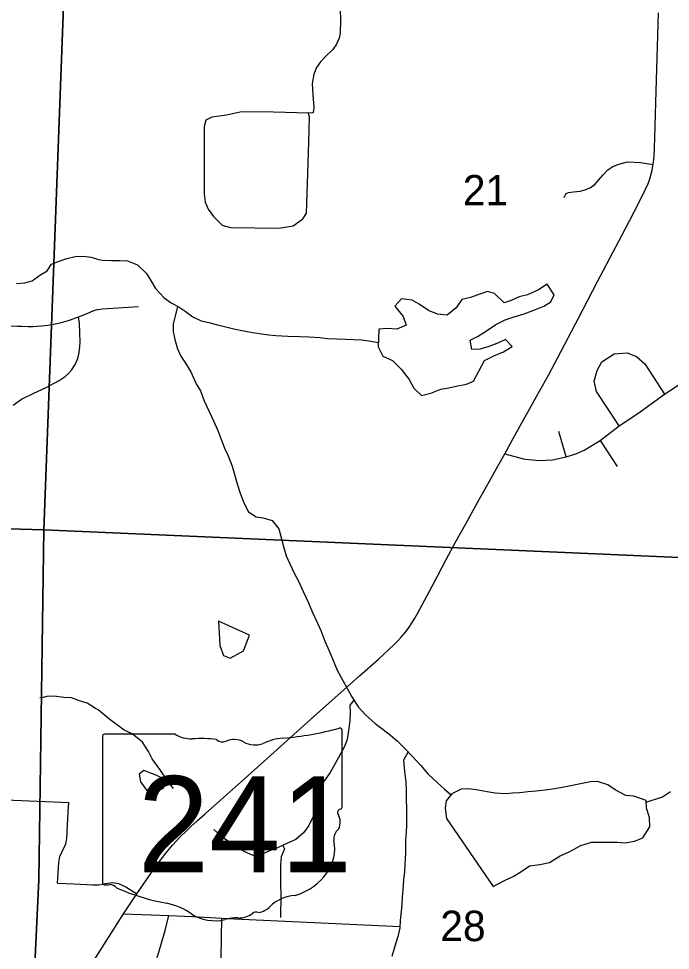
# Model space of a CAD drawing. Extents: x 0 to 34, y 0 to 22.
# Drawn here: x 5.169 to 6.064, y 16.375 to 17.654 of the extents above; entities that cross this region are included whole.
import ezdxf

# ---------------------------------------------------------------- set-up
doc = ezdxf.new("R2010")
doc.units = 0
for name, color, linetype in [('GM_X_Corporation', 7, 'Continuous'), ('GM_X_Minor_Lake', 7, 'Continuous'), ('GM_X_Minor_River', 7, 'Continuous'), ('GM_X_Section_Text', 7, 'Continuous'), ('GM_X_State_Location', 7, 'Continuous'), ('GM_X_State_Route', 7, 'Continuous'), ('GM_X_State_Shield', 7, 'Continuous'), ('GM_X_Township_Road', 7, 'Continuous')]:
    doc.layers.add(name, color=color, linetype=linetype)

msp = doc.modelspace()

# ---------------------------------------------------------------- linework, layer by layer
at = {"layer": 'GM_X_Corporation'}
for points in [[(4.2238, 17.9879), (5.2412, 17.9526), (5.2034, 16.9522), (4.1823, 16.9818)], [(5.2412, 17.9526), (6.2808, 17.9117), (6.2453, 16.9071), (5.2034, 16.9522)], [(5.2034, 16.9522), (5.1967, 16.4715), (5.1712, 15.9307), (4.1402, 15.964), (4.1823, 16.9818)], [(5.2034, 16.9522), (6.2453, 16.9071), (6.2042, 15.8911), (5.1712, 15.9307), (5.1967, 16.4715)]]:
    msp.add_lwpolyline(points, close=True, dxfattribs=at)
at = {"layer": 'GM_X_Minor_Lake'}
for points in [[(5.8087, 17.1849), (5.8219, 17.1912), (5.8351, 17.1967), (5.8468, 17.2041), (5.8379, 17.2138), (5.8281, 17.2091), (5.8164, 17.2044), (5.8028, 17.2004), (5.7915, 17.1999), (5.789, 17.2128), (5.7992, 17.2178), (5.8105, 17.2245), (5.8244, 17.2345), (5.8372, 17.2408), (5.8497, 17.2448), (5.8633, 17.2491), (5.8765, 17.2539), (5.8904, 17.2594), (5.9002, 17.2656), (5.9046, 17.2752), (5.895, 17.2895), (5.8829, 17.2821), (5.8682, 17.275), (5.8565, 17.2722), (5.8456, 17.2671), (5.8357, 17.2639), (5.8227, 17.2767), (5.8128, 17.2796), (5.7996, 17.2752), (5.7897, 17.2713), (5.7776, 17.2688), (5.7698, 17.2573), (5.7578, 17.2469), (5.7445, 17.2486), (5.7319, 17.2534), (5.7193, 17.2623), (5.7097, 17.2679), (5.6949, 17.2696), (5.6856, 17.2596), (5.6972, 17.2453), (5.7015, 17.2332), (5.6887, 17.2277), (5.6754, 17.2286), (5.6636, 17.2281), (5.6631, 17.2144), (5.6628, 17.2038), (5.6691, 17.1909), (5.6824, 17.1847), (5.6943, 17.1731), (5.7055, 17.1588), (5.7118, 17.1471), (5.7222, 17.1366), (5.7354, 17.1402), (5.749, 17.1453), (5.7599, 17.1474), (5.7698, 17.1498), (5.7842, 17.1523), (5.794, 17.1566)], [(5.794, 17.1566), (5.8087, 17.1849)], [(5.4434, 16.8268), (5.4453, 16.7934), (5.4504, 16.7798), (5.4596, 16.7761), (5.4777, 16.7863), (5.4861, 16.8077)], [(5.4861, 16.8077), (5.4434, 16.8268)], [(5.3411, 16.6217), (5.3347, 16.6167), (5.3363, 16.6061), (5.3464, 16.5925), (5.3563, 16.59), (5.3623, 16.595), (5.3683, 16.5986), (5.3675, 16.6042), (5.3643, 16.6122), (5.359, 16.6148)], [(5.359, 16.6148), (5.3411, 16.6217)], [(5.8208, 16.4624), (5.8363, 16.4706), (5.8483, 16.4761), (5.8589, 16.4827), (5.8709, 16.4909), (5.8849, 16.4926), (5.8982, 16.4954), (5.9128, 16.5048), (5.926, 16.5106), (5.9411, 16.5188), (5.9558, 16.5232), (5.9676, 16.5234), (5.9801, 16.5232), (5.9911, 16.5233), (6.0021, 16.5227), (6.015, 16.5248), (6.0263, 16.5295), (6.036, 16.5445), (6.0354, 16.5574), (6.0314, 16.5703), (6.0309, 16.5805), (6.0141, 16.5867), (6.0031, 16.5873), (5.9882, 16.5955), (5.9783, 16.6022), (5.9642, 16.6069), (5.9547, 16.6064), (5.9407, 16.6036), (5.9252, 16.6003), (5.9135, 16.5979), (5.9025, 16.5962), (5.8923, 16.5949), (5.8798, 16.5936), (5.8688, 16.5923), (5.857, 16.591), (5.8472, 16.5905), (5.8377, 16.59), (5.8236, 16.5909), (5.8126, 16.5923), (5.7974, 16.5955), (5.7864, 16.5968), (5.7769, 16.5963), (5.7641, 16.5897), (5.7563, 16.5801), (5.7549, 16.5702), (5.7566, 16.5558)], [(5.7566, 16.5558), (5.8208, 16.4624)], [(5.7566, 16.5558), (5.821, 16.4625)]]:
    msp.add_lwpolyline(points, dxfattribs=at)
at = {"layer": 'GM_X_Minor_River'}
for points in [[(5.1662, 17.2905), (5.1775, 17.2913), (5.1877, 17.2944), (5.1983, 17.302), (5.2082, 17.3078), (5.2142, 17.3173), (5.2248, 17.3215), (5.2354, 17.325), (5.2467, 17.3277), (5.2574, 17.3281), (5.2687, 17.3266), (5.2786, 17.3236), (5.2843, 17.3225)], [(5.2843, 17.3225), (5.2967, 17.3221), (5.3073, 17.3223), (5.3187, 17.3217), (5.3324, 17.3161), (5.3447, 17.3042), (5.3509, 17.2936), (5.3571, 17.2838), (5.3687, 17.2707), (5.3786, 17.264), (5.3882, 17.2588), (5.3977, 17.2525), (5.4081, 17.245), (5.4199, 17.2395), (5.4302, 17.237), (5.4405, 17.2345), (5.4538, 17.2312), (5.4648, 17.2283), (5.4778, 17.2255), (5.4907, 17.2234), (5.5025, 17.2217), (5.5128, 17.2203), (5.5222, 17.2193), (5.5386, 17.2184), (5.5549, 17.2178), (5.5678, 17.2173), (5.5826, 17.2163), (5.5932, 17.2153), (5.6061, 17.2147), (5.6179, 17.2142), (5.6289, 17.2139), (5.6399, 17.2133), (5.6502, 17.2119), (5.6631, 17.2095)], [(5.3874, 17.2592), (5.3813, 17.2348), (5.3811, 17.2249), (5.3835, 17.2139), (5.3871, 17.201), (5.3918, 17.1908), (5.398, 17.181), (5.4053, 17.1694), (5.4128, 17.1528), (5.4186, 17.143), (5.4237, 17.1294), (5.4307, 17.115), (5.4366, 17.1018), (5.4428, 17.0886), (5.448, 17.0742), (5.4523, 17.0636), (5.457, 17.0538), (5.4621, 17.0398), (5.4661, 17.027), (5.4692, 17.0156), (5.4732, 17.0028), (5.4783, 16.9895), (5.4846, 16.9771), (5.4953, 16.97), (5.5048, 16.9686), (5.5174, 16.965), (5.5262, 16.9537), (5.5302, 16.9401), (5.5326, 16.9295), (5.5366, 16.9167), (5.5413, 16.9057), (5.5479, 16.8921), (5.5534, 16.8819), (5.56, 16.8676), (5.5671, 16.8521), (5.5726, 16.8389), (5.5796, 16.8242), (5.5839, 16.814), (5.5894, 16.7996), (5.5957, 16.786), (5.6, 16.7754), (5.6066, 16.7596), (5.6121, 16.7494), (5.6191, 16.737), (5.6265, 16.723), (5.6354, 16.7091), (5.645, 16.6986), (5.6585, 16.6862), (5.6696, 16.678), (5.6796, 16.6702), (5.6895, 16.662), (5.6999, 16.6518), (5.7095, 16.6417), (5.7211, 16.629), (5.7315, 16.6166), (5.7438, 16.6053), (5.7538, 16.5964), (5.7632, 16.5886)], [(5.2784, 16.7052), (5.2746, 16.7071), (5.2632, 16.7143), (5.2526, 16.7177), (5.2416, 16.7214), (5.231, 16.7221), (5.2211, 16.7236), (5.2097, 16.7239), (5.1991, 16.7213), (5.1987, 16.722)], [(5.6293, 16.7186), (5.624, 16.7116), (5.6245, 16.7017), (5.6239, 16.6899), (5.6222, 16.6766), (5.6201, 16.6644), (5.616, 16.6537), (5.6035, 16.6307), (5.5968, 16.6192), (5.589, 16.6081), (5.5827, 16.5951), (5.5791, 16.5787), (5.5752, 16.5623), (5.5674, 16.5463), (5.5604, 16.5363), (5.5499, 16.527), (5.534, 16.52), (5.5238, 16.5153), (5.5137, 16.5113), (5.5008, 16.5054), (5.491, 16.5049), (5.4795, 16.5101), (5.4638, 16.5197), (5.4501, 16.5294), (5.437, 16.541)], [(5.3816, 16.5972), (5.3739, 16.6074), (5.3634, 16.6228), (5.3526, 16.6378), (5.3472, 16.648), (5.339, 16.6608), (5.3248, 16.6724), (5.3141, 16.6772), (5.3047, 16.6842), (5.2947, 16.6912), (5.2784, 16.7052)], [(5.7041, 16.6475), (5.6975, 16.6359), (5.6992, 16.6207), (5.7009, 16.6063), (5.7014, 16.5941), (5.7019, 16.5576), (5.7017, 16.5474), (5.7011, 16.5367), (5.7005, 16.5257), (5.7003, 16.5082), (5.6994, 16.4926), (5.6988, 16.4831), (5.6978, 16.4717), (5.6968, 16.458), (5.6958, 16.4485), (5.6952, 16.4375), (5.6932, 16.4158), (5.6926, 16.4059), (5.6898, 16.3937), (5.6858, 16.3807), (5.6814, 16.3662)], [(6.031, 16.5784), (6.0536, 16.5858), (6.0645, 16.5931)], [(5.5319, 16.519), (5.5341, 16.5143), (5.5297, 16.5032), (5.5287, 16.4925), (5.5286, 16.4758), (5.529, 16.4412), (5.5288, 16.4298), (5.5289, 16.42)]]:
    msp.add_lwpolyline(points, dxfattribs=at)
at = {"layer": 'GM_X_State_Route'}
for points in [[(5.9642, 17.2932), (5.9725, 17.309), (6.002, 17.3654), (6.0214, 17.4022), (6.0302, 17.4201), (6.0337, 17.428), (6.0359, 17.4342), (6.0387, 17.4443), (6.0407, 17.4542), (6.042, 17.4649), (6.0426, 17.4763), (6.0432, 17.5064), (6.0441, 17.5394), (6.048, 17.6624)], [(5.3131, 16.4252), (5.3312, 16.4526), (5.3577, 16.4907), (5.371, 16.5082), (5.3803, 16.5194), (5.3907, 16.5305), (5.3986, 16.5382), (5.4061, 16.5452), (5.4147, 16.5531), (5.4251, 16.5623), (5.4462, 16.5813), (5.4749, 16.6069), (5.5058, 16.6341), (5.57, 16.6918), (5.637, 16.7516), (5.6632, 16.7749), (5.6849, 16.7949), (5.6898, 16.7998), (5.6942, 16.8046), (5.6974, 16.8082), (5.7003, 16.8118), (5.7053, 16.8186), (5.7096, 16.8251), (5.7132, 16.8312), (5.7168, 16.8375), (5.7202, 16.8435), (5.7233, 16.8495), (5.7332, 16.8679), (5.7442, 16.8887), (5.7564, 16.9118), (5.7696, 16.9362), (5.7833, 16.9607), (5.7994, 16.9897), (5.8157, 17.019), (5.8273, 17.0396), (5.8369, 17.0567), (5.8512, 17.0828), (5.8805, 17.1355), (5.8967, 17.1648), (5.9097, 17.189), (5.9379, 17.243), (5.9504, 17.2668), (5.9642, 17.2932)], [(5.2042, 16.248), (5.2124, 16.2632), (5.2218, 16.279), (5.232, 16.2955), (5.2494, 16.3232), (5.2656, 16.3495), (5.2775, 16.3685), (5.2957, 16.3977), (5.3131, 16.4252)]]:
    msp.add_lwpolyline(points, dxfattribs=at)
at = {"layer": 'GM_X_State_Shield'}
for p, q in [((5.6136, 16.572), (5.6136, 16.6766)), ((5.284, 16.6682), (5.284, 16.4681)), ((5.3838, 16.6717), (5.2872, 16.6717)), ((5.6136, 16.572), (5.6136, 16.572))]:
    msp.add_line(p, q, dxfattribs=at)
for centre, major_axis, start_param, end_param in [((5.4962, 16.9445), (0.3495, 0), 4.814394, 5.042369), ((5.6099, 16.6771), (0.00367, 0), 6.141152, 7.989035), ((5.2878, 16.6687), (0.00382, 0), 1.712693, 3.28349), ((5.4068, 16.6949), (0.037, 0), 4.042523, 4.731795), ((5.419, 16.5593), (0.133, 0), 1.404758, 1.657858), ((5.4492, 16.6697), (0.0107, 0), 3.836095, 5.185415), ((5.4649, 16.6466), (0.0222, 0), 0.950623, 2.079405), ((5.4936, 16.6783), (0.0267, 0), 4.081561, 5.145723), ((5.5408, 16.6106), (0.0703, 0), 1.699011, 2.107814), ((5.6097, 16.5716), (0.00393, 0), 5.05454, 6.418171), ((5.6127, 16.5643), (0.00568, 0), 1.883978, 3.671073), ((5.5766, 16.551), (0.0341, 0), 5.934695, 6.695948), ((5.6267, 16.5281), (0.0248, 0), 2.387724, 3.262537), ((5.5158, 16.5148), (0.0874, 0), 5.101752, 6.440018), ((5.2878, 16.4677), (0.00385, 0), 3.00124, 4.508301), ((5.2884, 16.4882), (0.0294, 0), 4.665946, 4.897461), ((5.2944, 16.4566), (0.0106, 0), 0.519207, 1.627899), ((5.4282, 16.6364), (0.2524, 0), 4.195997, 4.488961), ((5.5526, 16.4119), (0.0479, 0), 1.647645, 2.488434), ((5.353, 16.3782), (0.079, 0), 0.823519, 1.323587), ((5.492, 16.4487), (0.0282, 0), 4.937069, 5.64225), ((5.4384, 16.4556), (0.0501, 0), 4.026481, 4.996735), ((5.4674, 16.3864), (0.0412, 0), 1.495662, 1.94098), ((5.471, 16.4406), (0.0267, 0), 4.691044, 5.507374), ((5.4952, 16.4212), (0.00752, 0), 1.147584, 2.315152)]:
    msp.add_ellipse(centre, major_axis=major_axis, ratio=0.8, start_param=start_param, end_param=end_param, dxfattribs=at)
at = {"layer": 'GM_X_Township_Road'}
for p, q in [((5.921, 17.0526), (5.9109, 17.0874)), ((5.9679, 17.0752), (5.991, 17.0392)), ((5.4557, 16.4187), (5.6929, 16.4076))]:
    msp.add_line(p, q, dxfattribs=at)
for points in [[(5.6104, 17.6776), (5.6112, 17.6534), (5.6108, 17.6346), (5.6091, 17.6276), (5.6056, 17.6192), (5.6007, 17.612), (5.5967, 17.6083)], [(5.5967, 17.6083), (5.5928, 17.6045), (5.5834, 17.5949), (5.5783, 17.5872), (5.5746, 17.5783), (5.5721, 17.5652), (5.573, 17.5496), (5.5743, 17.5328), (5.5735, 17.5252), (5.5668, 17.5245), (5.5357, 17.5255)], [(5.5357, 17.5255), (5.5192, 17.5261), (5.4751, 17.5263), (5.4547, 17.5218), (5.4342, 17.5189), (5.4262, 17.5149), (5.4237, 17.5062), (5.424, 17.4864), (5.424, 17.4427), (5.4238, 17.4235)], [(5.5661, 17.4415), (5.5674, 17.4846), (5.5687, 17.5194), (5.567, 17.5239)], [(5.9184, 17.4089), (5.921, 17.414), (5.9243, 17.4158), (5.931, 17.4163), (5.9405, 17.4173), (5.9474, 17.4191), (5.9538, 17.4222), (5.9599, 17.4263), (5.9655, 17.4324), (5.9717, 17.4398), (5.9783, 17.4467), (5.985, 17.4511), (5.9935, 17.4547), (6.0052, 17.4575), (6.0233, 17.457), (6.0407, 17.4542)], [(5.4513, 17.3698), (5.4602, 17.3676), (5.5266, 17.3665), (5.5461, 17.3697), (5.5594, 17.3795), (5.5645, 17.3874), (5.5661, 17.4415)], [(5.4238, 17.4235), (5.4237, 17.4134), (5.4251, 17.4022), (5.4295, 17.3925), (5.4367, 17.3827), (5.4486, 17.3705), (5.4513, 17.3698)], [(5.1419, 17.2309), (5.1505, 17.2323), (5.1671, 17.2322), (5.1728, 17.2318), (5.182, 17.2317), (5.1891, 17.2316), (5.194, 17.2319), (5.2007, 17.2325), (5.2093, 17.2336), (5.2169, 17.2348), (5.2259, 17.2367), (5.239, 17.2403), (5.2514, 17.2448), (5.2629, 17.2495), (5.2724, 17.2534), (5.2774, 17.2549), (5.284, 17.2558), (5.3334, 17.2589)], [(5.1616, 17.1237), (5.1728, 17.1318), (5.1899, 17.1398), (5.2067, 17.1478), (5.2248, 17.1573), (5.2331, 17.163), (5.2375, 17.1671), (5.2414, 17.1716), (5.2466, 17.1795), (5.2501, 17.1876), (5.2518, 17.1937), (5.2532, 17.203), (5.2534, 17.2111), (5.2531, 17.222), (5.2524, 17.2361), (5.2514, 17.2448)], [(5.9941, 17.0952), (5.9627, 17.1421), (5.9596, 17.1566), (5.9638, 17.1712), (5.97, 17.1831), (5.9868, 17.1938), (6.0048, 17.1953), (6.0175, 17.1903), (6.029, 17.1804), (6.056, 17.1388)], [(5.8656, 17.0493), (5.8841, 17.0477), (5.9023, 17.0485), (5.921, 17.0526), (5.9344, 17.0567), (5.946, 17.0617), (5.9679, 17.0752), (5.9941, 17.0952), (6.0197, 17.112), (6.056, 17.1388), (6.0885, 17.1602), (6.0893, 17.1608)], [(5.8369, 17.0567), (5.8627, 17.0496), (5.8656, 17.0493)], [(5.0114, 16.5239), (5.0161, 16.5306), (5.0223, 16.5369), (5.0265, 16.5422), (5.0444, 16.5518), (5.0748, 16.564), (5.0872, 16.5705), (5.1058, 16.578), (5.1139, 16.5802), (5.1241, 16.5814), (5.1375, 16.5817), (5.1619, 16.5811), (5.2381, 16.5778)], [(5.2225, 16.4669), (5.224, 16.4956), (5.2256, 16.5039), (5.2293, 16.5113), (5.2339, 16.5209), (5.2352, 16.5285), (5.2369, 16.5644), (5.2381, 16.5778)], [(5.2225, 16.4669), (5.245, 16.4661), (5.2709, 16.4646), (5.2796, 16.4648), (5.2877, 16.4667), (5.2981, 16.468), (5.3062, 16.4667), (5.316, 16.4622), (5.3312, 16.4526)], [(5.3131, 16.4252), (5.3755, 16.4227), (5.408, 16.4211)], [(5.3507, 16.0076), (5.3553, 16.1451), (5.3563, 16.2096), (5.3572, 16.2474), (5.3546, 16.2591), (5.3391, 16.298), (5.34, 16.3082), (5.3463, 16.3143), (5.3602, 16.3677), (5.3704, 16.4019), (5.3755, 16.4227)], [(5.408, 16.4211), (5.4481, 16.4191), (5.4557, 16.4187)], [(5.4354, 16.004), (5.4403, 16.1421), (5.443, 16.2442), (5.4461, 16.336), (5.4472, 16.365), (5.4481, 16.4191)]]:
    msp.add_lwpolyline(points, dxfattribs=at)

# ---------------------------------------------------------------- texts
at = {"layer": 'GM_X_Section_Text'}
for s, p in [('21', (5.7791, 17.3978)), ('28', (5.7482, 16.3875))]:
    msp.add_text(s, height=0.04186, rotation=0, dxfattribs=at).set_placement(p)
at = {"layer": 'GM_X_State_Location'}
for s in ['s', 'r']:
    msp.add_text(s, height=0.000189, dxfattribs=at).set_placement((5.4451, 16.5549))
msp.add_text('241', height=0.000189, rotation=0, dxfattribs=at).set_placement((5.3782, 16.5411))
at = {"layer": 'GM_X_State_Shield'}
msp.add_text('241', height=0.13184, dxfattribs=at).set_placement((5.3326, 16.4822))

doc.saveas('drawing.dxf')
